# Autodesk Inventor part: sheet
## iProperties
Created: 2007-11
Part Number: sheet
Document SubType Name: Modeling
Designer: Administrateur
Author: Administrateur
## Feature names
1. Extrusion1
2. Extrusion3
3. Hole2
4. Hole3
